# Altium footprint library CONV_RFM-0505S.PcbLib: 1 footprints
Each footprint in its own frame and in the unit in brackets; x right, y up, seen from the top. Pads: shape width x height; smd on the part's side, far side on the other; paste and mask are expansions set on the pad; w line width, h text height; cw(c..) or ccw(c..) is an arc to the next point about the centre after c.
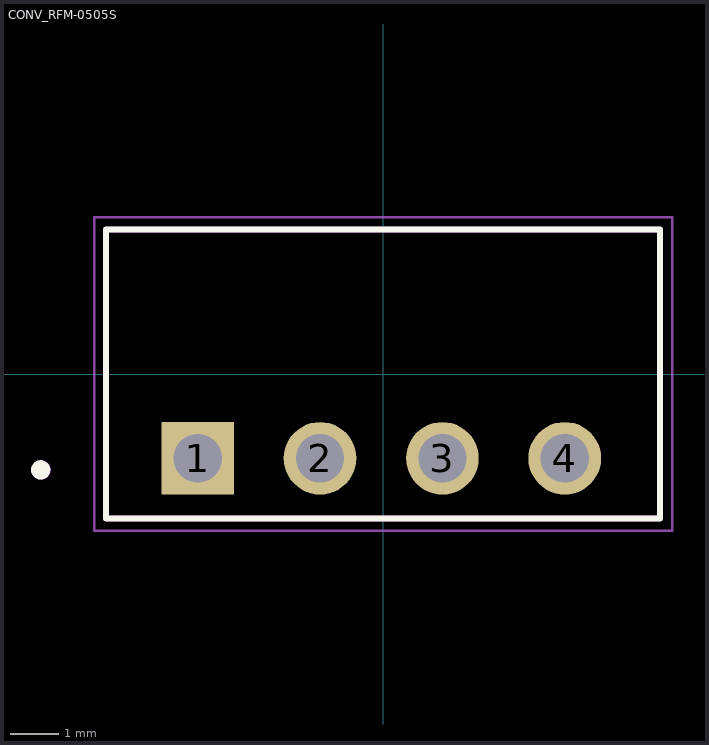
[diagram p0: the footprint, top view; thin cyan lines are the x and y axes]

## CONV_RFM-0505S [mm]
height 10
pads (4):
  rect 1.508x1.508 / inner round 1.508 / far side rect 1.508x1.508 hole 1: 1(-3.85,-1.75)
  round 1.508 hole 1: 2(-1.31,-1.75) 3(1.23,-1.75) 4(3.77,-1.75)
Top Overlay:
  circle w0.2: c-7.11,-1.99 r0.1
  lines w0.127: -5.75,-3 -5.75,3 5.75,3 5.75,-3 -5.75,-3
Assembly Top:
  circle w0.2: c-7.1,-1.99 r0.1
  lines w0.127: -5.75,-3 -5.75,3 5.75,3 5.75,-3 -5.75,-3
Courtyard Top:
  lines w0.05: -6,-3.25 -6,3.25 6,3.25 6,-3.25 -6,-3.25
3D body "step_temp.STEP": height 9.5, standoff -4.6, extent -5.75,-3 5.75,3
